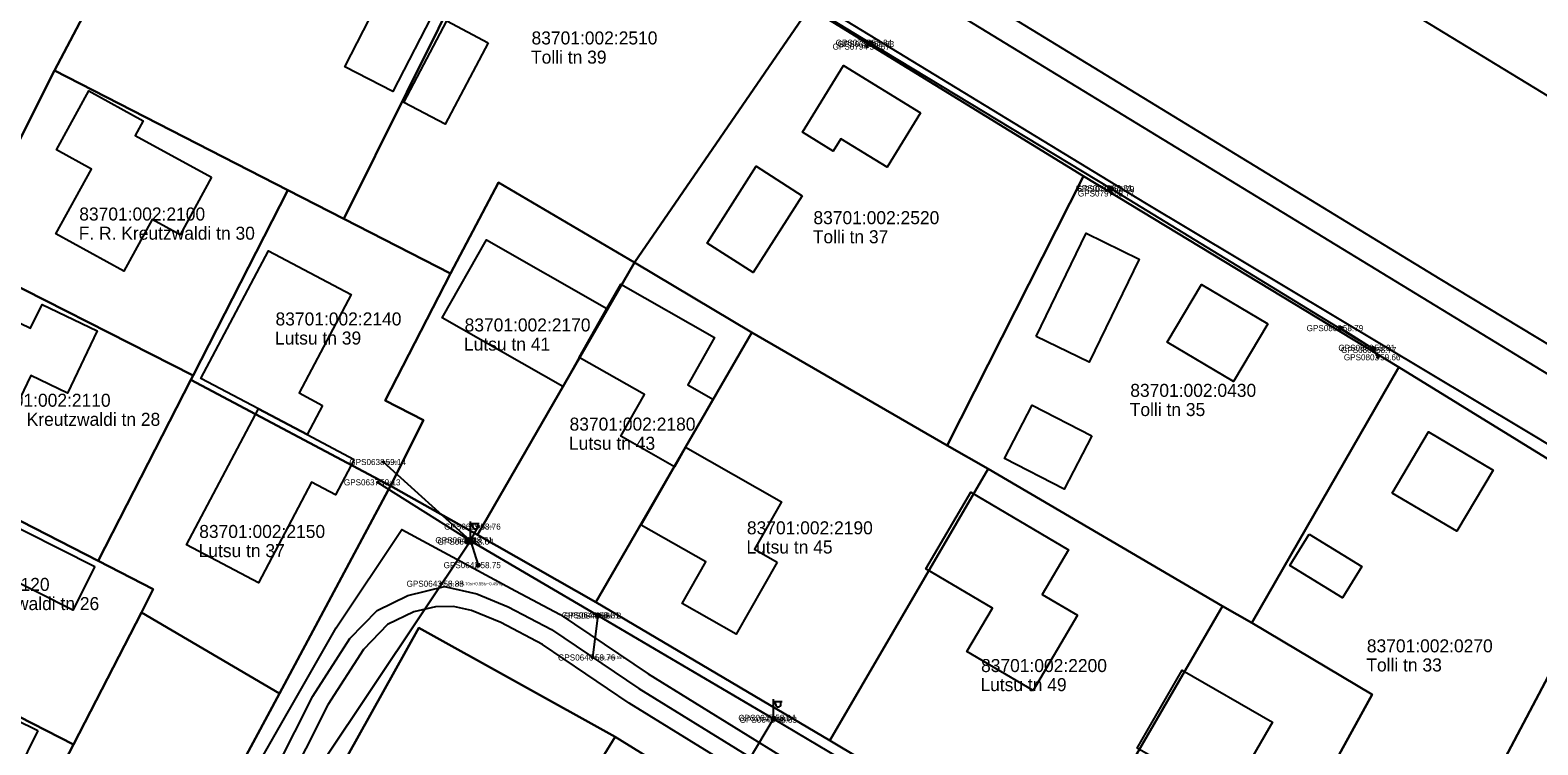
# Model space of a CAD drawing. Extents: x 580119 to 583377, y 6518915 to 6520820.
# Drawn here: x 581772.7 to 581946.3, y 6520373 to 6520455.4 of the extents above; entities that cross this region are included whole.
import ezdxf

# ---------------------------------------------------------------- set-up
doc = ezdxf.new("R2010")
doc.units = 0
for name, color, linetype in [('Hoone Elu- või ühiskondlik hoone', 7, 'Continuous'), ('Hoone Kõrval- või tootmishoone', 7, 'Continuous'), ('L_AADRESS', 7, 'Continuous'), ('MAAMUDEL', 7, 'Continuous'), ('MOOTKORG-EH2000', 7, 'Continuous'), ('MOOTMPUNKT', 7, 'Continuous'), ('MOOTNR', 7, 'Continuous'), ('MPOHULIIN', 7, 'Continuous'), ('Muu rajatis Katusealune', 7, 'Continuous'), ('PIIR', 7, 'Continuous'), ('POST', 7, 'Continuous'), ('Rippe kõrgus', 7, 'Continuous'), ('SIOHULIIN', 7, 'Continuous'), ('SIRAJATIS', 7, 'Continuous'), ('Tee Liiklusala', 7, 'Continuous'), ('Tee Tänav Püsikate', 7, 'Continuous'), ('TUNNUS', 7, 'Continuous')]:
    doc.layers.add(name, color=color, linetype=linetype)

msp = doc.modelspace()

# ---------------------------------------------------------------- linework, layer by layer
at = {"layer": 'Hoone Elu- või ühiskondlik hoone'}
for points in [[(581875.22, 6520445.82), (581871.37, 6520439.57), (581866.03, 6520442.86), (581865.14, 6520441.43), (581861.61, 6520443.61), (581866.34, 6520451.29)], [(581793.56, 6520438.41), (581789.93, 6520431.77), (581786.72, 6520433.53), (581783.46, 6520427.59), (581775.63, 6520431.89), (581779.72, 6520439.34), (581775.68, 6520441.56), (581779.41, 6520448.36), (581785.68, 6520444.93), (581784.75, 6520443.23)], [(581835.89, 6520417.66), (581834, 6520414.32), (581820.1, 6520422.21), (581825.21, 6520431.2), (581839.1, 6520423.3)], [(581806.32, 6520412.13), (581804.55, 6520408.77), (581798.95, 6520411.72), (581792.33, 6520415.21), (581800.1, 6520429.92), (581809.62, 6520424.9), (581803.63, 6520413.56)], [(581848.14, 6520407.3), (581846.87, 6520405.06), (581840.68, 6520408.58), (581843.41, 6520413.38), (581835.89, 6520417.66), (581839.1, 6520423.3), (581840.69, 6520426.09), (581851.49, 6520419.95), (581848.4, 6520414.5), (581851.3, 6520412.85)], [(581915.21, 6520421.53), (581911.28, 6520414.89), (581903.64, 6520419.42), (581907.57, 6520426.07)], [(581766.49, 6520424.01), (581772.7, 6520421.03), (581774.02, 6520423.77), (581780.39, 6520420.71), (581776.95, 6520413.54), (581772.73, 6520415.56), (581768.25, 6520406.24), (581759.9, 6520410.25)], [(581809.98, 6520405.89), (581807.83, 6520401.82), (581805.07, 6520403.27), (581798.94, 6520391.68), (581790.66, 6520396.05), (581798.95, 6520411.72), (581804.55, 6520408.77)], [(581929.56, 6520402.03), (581933.74, 6520409.08), (581941.18, 6520404.66), (581937, 6520397.62)], [(581858.71, 6520394.08), (581853.98, 6520385.76), (581847.77, 6520389.29), (581850.5, 6520394.1), (581843.05, 6520398.33), (581846.87, 6520405.06), (581848.14, 6520407.3), (581859.21, 6520401), (581856.11, 6520395.55)], [(581893.3, 6520387.96), (581888.2, 6520379.29), (581880.57, 6520383.78), (581883.5, 6520388.76), (581875.81, 6520393.3), (581881, 6520402.11), (581892.26, 6520395.49), (581889.23, 6520390.35)], [(581915.6, 6520368.18), (581911.32, 6520360.75), (581905.69, 6520363.98), (581908.05, 6520368.09), (581900.19, 6520372.62), (581905.37, 6520381.61), (581915.75, 6520375.63), (581912.49, 6520369.96)]]:
    msp.add_lwpolyline(points, close=True, dxfattribs=at)
at = {"layer": 'Hoone Kõrval- või tootmishoone'}
for points in [[(581819.45, 6520458.04), (581814.45, 6520448.29), (581808.89, 6520451.14), (581813.9, 6520460.89)], [(581825.43, 6520453.92), (581820.46, 6520444.52), (581815.7, 6520447.04), (581820.64, 6520456.44)], [(581861.58, 6520436.29), (581855.93, 6520427.45), (581850.64, 6520430.83), (581856.28, 6520439.68)], [(581888.52, 6520420.07), (581894.28, 6520431.96), (581900.41, 6520428.99), (581894.65, 6520417.1)], [(581894.94, 6520408.63), (581891.77, 6520402.47), (581884.9, 6520406.02), (581888.08, 6520412.17)], [(581780.11, 6520393.55), (581777.57, 6520388.54), (581765.58, 6520394.57), (581768.12, 6520399.6)], [(581773.53, 6520374.68), (581771.16, 6520369.84), (581758.58, 6520375.99), (581760.95, 6520380.84)]]:
    msp.add_lwpolyline(points, close=True, dxfattribs=at)
at = {"layer": 'MOOTMPUNKT'}
for centre in [(581869.08, 6520453.47), (581869.35, 6520453.92), (581869.57, 6520453.77), (581897.01, 6520437.16), (581897.24, 6520437.06), (581897.26, 6520436.55), (581923.61, 6520421.03), (581927.27, 6520418.76), (581927.43, 6520418.52), (581927.9, 6520417.67), (581813.34, 6520405.6), (581812.71, 6520403.26), (581824.26, 6520398.16), (581823.32, 6520396.59), (581823.44, 6520396.42), (581824.27, 6520393.72), (581820, 6520391.58), (581837.95, 6520387.95), (581838.14, 6520387.89), (581837.45, 6520383.08), (581858.22, 6520376.12), (581858.37, 6520375.9)]:
    msp.add_circle(centre, 0.1, dxfattribs=at)
at = {"layer": 'MPOHULIIN'}
for p, q in [((581869.46, 6520453.85), (581869.08, 6520453.47)), ((581897.12, 6520437.11), (581897.26, 6520436.55)), ((581823.38, 6520396.51), (581813.34, 6520405.6)), ((581812.71, 6520403.26), (581823.38, 6520396.51)), ((581823.38, 6520396.51), (581824.26, 6520398.16)), ((581838.05, 6520387.92), (581837.45, 6520383.08))]:
    msp.add_line(p, q, dxfattribs=at)
for points in [[(581788.5, 6520502.77), (581814.76, 6520487.31), (581837.78, 6520473.2), (581869.46, 6520453.85), (581897.12, 6520437.11), (581927.35, 6520418.64), (581927.9, 6520417.67)], [(581789.29, 6520345.21), (581806.35, 6520371.05), (581823.38, 6520396.51), (581838.05, 6520387.92), (581858.29, 6520376.01), (581878.69, 6520363.88), (581896.57, 6520352.92)]]:
    msp.add_lwpolyline(points, dxfattribs=at)
at = {"layer": 'Muu rajatis Katusealune'}
msp.add_lwpolyline([(581919.98, 6520397.29), (581926.05, 6520393.58), (581923.84, 6520389.96), (581917.77, 6520393.68)], close=True, dxfattribs=at)
at = {"layer": 'PIIR'}
for points in [[(581372.45, 6520790.36), (581408.38, 6520769.85), (581413.58, 6520742.25), (581463.7, 6520713.56), (581523.82, 6520679.13), (581549.51, 6520667), (581649.11, 6520606.32), (581652.65, 6520627.42), (582182.6, 6520304.58), (582184, 6520303.69), (582181.07, 6520288.42), (582278.18, 6520283.9), (582336.7, 6520285.99)], [(581799.11, 6520495.6), (581775.47, 6520450.71), (581764.63, 6520429.16)], [(582284.12, 6520257.02), (582261.11, 6520257.72), (582237.89, 6520257.97), (582223.55, 6520256.24), (582192.17, 6520260.67), (582164.12, 6520273.34), (582126.68, 6520296.88), (582094.75, 6520316.22), (582063.67, 6520335.59), (582031.69, 6520354.73), (581999.92, 6520374.14), (581993.27, 6520378.24), (581957.49, 6520399.79), (581930.32, 6520416.52), (581894, 6520438.54), (581862.44, 6520457.93)], [(581785.35, 6520349.14), (581801.36, 6520378.94), (581814.15, 6520402.85), (581824.17, 6520397.21), (581837.82, 6520389.46), (581864.77, 6520373.51), (581891.69, 6520357.4)]]:
    msp.add_lwpolyline(points, dxfattribs=at)
for points in [[(581830.55, 6520477.44), (581808.78, 6520433.62), (581802.33, 6520436.92), (581775.47, 6520450.71), (581799.11, 6520495.6)], [(581830.55, 6520477.44), (581862.44, 6520457.93), (581842.26, 6520428.59), (581826.59, 6520437.81), (581821.07, 6520427.33), (581808.78, 6520433.62)], [(581862.44, 6520457.93), (581894, 6520438.54), (581878.29, 6520407.51), (581855.8, 6520420.54), (581842.26, 6520428.59)], [(581775.47, 6520450.71), (581802.33, 6520436.92), (581791.42, 6520415.56), (581764.63, 6520429.16)], [(581821.07, 6520427.33), (581826.59, 6520437.81), (581842.26, 6520428.59), (581824.17, 6520397.21), (581814.15, 6520402.85), (581817.98, 6520410.44), (581813.53, 6520412.71)], [(581878.29, 6520407.51), (581894, 6520438.54), (581930.32, 6520416.52), (581913.4, 6520387.09), (581910, 6520388.99), (581883.02, 6520404.8)], [(581791.42, 6520415.56), (581802.33, 6520436.92), (581808.78, 6520433.62), (581821.07, 6520427.33), (581813.53, 6520412.71), (581817.98, 6520410.44), (581814.15, 6520402.85), (581791.17, 6520415.07)], [(581764.63, 6520429.16), (581791.42, 6520415.56), (581791.17, 6520415.07), (581780.5, 6520394.2), (581753.86, 6520407.85)], [(581842.26, 6520428.59), (581855.8, 6520420.54), (581837.82, 6520389.46), (581824.17, 6520397.21)], [(581855.8, 6520420.54), (581878.29, 6520407.51), (581883.02, 6520404.8), (581864.77, 6520373.51), (581837.82, 6520389.46)], [(581930.32, 6520416.52), (581957.49, 6520399.79), (581932.94, 6520353.26), (581931.31, 6520350.19), (581927.81, 6520351.97), (581921.06, 6520341.05), (581910.1, 6520322.74), (581906.17, 6520340.51), (581909.67, 6520346.83), (581927.24, 6520378.81), (581913.4, 6520387.09)], [(581791.17, 6520415.07), (581814.15, 6520402.85), (581801.36, 6520378.94), (581785.47, 6520388.28), (581786.84, 6520390.94), (581780.5, 6520394.2)], [(581753.86, 6520407.85), (581780.5, 6520394.2), (581786.84, 6520390.94), (581785.47, 6520388.28), (581777.64, 6520373.06), (581744.38, 6520390.07)], [(581883.02, 6520404.8), (581910, 6520388.99), (581891.69, 6520357.4), (581864.77, 6520373.51)], [(581957.49, 6520399.79), (581993.27, 6520378.24), (581969.51, 6520335.03), (581932.94, 6520353.26)], [(581744.38, 6520390.07), (581777.64, 6520373.06), (581769.84, 6520358.07), (581768.32, 6520355.34), (581735.49, 6520372.19)], [(581910, 6520388.99), (581913.4, 6520387.09), (581927.24, 6520378.81), (581909.67, 6520346.83), (581891.69, 6520357.4)], [(581769.84, 6520358.07), (581777.64, 6520373.06), (581785.47, 6520388.28), (581801.36, 6520378.94), (581785.35, 6520349.14), (581782.27, 6520350.98), (581774.1, 6520355.46)], [(581817.44, 6520386.49), (581840.03, 6520373.94), (581829.56, 6520356.9), (581832.75, 6520354.9), (581821.38, 6520336.91), (581798.19, 6520351.98)], [(581798.19, 6520351.98), (581821.38, 6520336.91), (581844, 6520323.04), (581878.03, 6520302.4), (581885.96, 6520304.82), (581899.19, 6520326.8), (581895.57, 6520340), (581865.29, 6520358.29), (581840.03, 6520373.94), (581817.44, 6520386.49)], [(581832.75, 6520354.9), (581829.56, 6520356.9), (581840.03, 6520373.94), (581865.29, 6520358.29), (581844, 6520323.04), (581821.38, 6520336.91)]]:
    msp.add_lwpolyline(points, close=True, dxfattribs=at)
at = {"layer": 'POST'}
for p, q in [((581823.38, 6520396.76), (581823.38, 6520398.76)), ((581823.38, 6520398.51), (581824.38, 6520398.51)), ((581823.6, 6520398.19), (581823.6, 6520398.51)), ((581824.22, 6520398.19), (581824.22, 6520398.51)), ((581823.38, 6520396.51), (581823.38, 6520396.51)), ((581858.29, 6520376.26), (581858.29, 6520378.26)), ((581858.29, 6520378.01), (581859.29, 6520378.01)), ((581858.52, 6520377.69), (581858.52, 6520378.01)), ((581859.13, 6520377.69), (581859.13, 6520378.01)), ((581858.29, 6520376.01), (581858.29, 6520376.01))]:
    msp.add_line(p, q, dxfattribs=at)
for points in [[(581927.35, 6520418.64), (581923.61, 6520421.03)], [(581823.38, 6520396.51), (581824.27, 6520393.72)]]:
    msp.add_lwpolyline(points, dxfattribs=at)
for centre, radius in [((581869.46, 6520453.85), 0.25), ((581897.12, 6520437.11), 0.25), ((581923.61, 6520421.03), 0.2), ((581927.35, 6520418.64), 0.25), ((581823.38, 6520396.51), 0.25), ((581824.27, 6520393.72), 0.2), ((581838.05, 6520387.92), 0.25), ((581858.29, 6520376.01), 0.25)]:
    msp.add_circle(centre, radius, dxfattribs=at)
for centre in [(581823.91, 6520398.19), (581858.83, 6520377.69)]:
    msp.add_arc(centre, 0.306, 180, 0, dxfattribs=at)
at = {"layer": 'SIOHULIIN'}
for points in [[(581689.69, 6520563.6), (581714.9, 6520547.97), (581754.92, 6520523.74), (581788.5, 6520502.77), (581814.76, 6520487.31), (581837.78, 6520473.2), (581869.46, 6520453.85), (581897.12, 6520437.11), (581927.35, 6520418.64)], [(581851.67, 6520364.92), (581858.29, 6520376.01), (581838.05, 6520387.92), (581823.38, 6520396.51), (581806.35, 6520371.05), (581789.29, 6520345.21), (581821.56, 6520325.5), (581843.02, 6520312.69)]]:
    msp.add_lwpolyline(points, dxfattribs=at)
at = {"layer": 'SIRAJATIS'}
msp.add_lwpolyline([(581822.88, 6520396.81), (581823.88, 6520396.81), (581823.88, 6520396.21), (581822.88, 6520396.21)], close=True, dxfattribs=at)
for centre, radius in [((581823.18, 6520396.51), 0.0304), ((581823.18, 6520396.51), 0.029), ((581823.18, 6520396.51), 0.0277), ((581823.18, 6520396.51), 0.0263), ((581823.18, 6520396.51), 0.0249), ((581823.18, 6520396.51), 0.0236), ((581823.18, 6520396.51), 0.0222), ((581823.18, 6520396.51), 0.0209), ((581823.18, 6520396.51), 0.0195), ((581823.18, 6520396.51), 0.0181), ((581823.18, 6520396.51), 0.0168), ((581823.18, 6520396.51), 0.0154), ((581823.18, 6520396.51), 0.014), ((581823.18, 6520396.51), 0.0127), ((581823.18, 6520396.51), 0.0113), ((581823.18, 6520396.51), 0.00996), ((581823.18, 6520396.51), 0.0086), ((581823.18, 6520396.51), 0.00724), ((581823.18, 6520396.51), 0.00587), ((581823.18, 6520396.51), 0.00451), ((581823.18, 6520396.51), 0.00315), ((581823.18, 6520396.51), 0.00179), ((581823.18, 6520396.51), 0.000426), ((581823.58, 6520396.51), 0.0304), ((581823.58, 6520396.51), 0.029), ((581823.58, 6520396.51), 0.0277), ((581823.58, 6520396.51), 0.0263), ((581823.58, 6520396.51), 0.0249), ((581823.58, 6520396.51), 0.0236), ((581823.58, 6520396.51), 0.0222), ((581823.58, 6520396.51), 0.0209), ((581823.58, 6520396.51), 0.0195), ((581823.58, 6520396.51), 0.0181), ((581823.58, 6520396.51), 0.0168), ((581823.58, 6520396.51), 0.0154), ((581823.58, 6520396.51), 0.014), ((581823.58, 6520396.51), 0.0127), ((581823.58, 6520396.51), 0.0113), ((581823.58, 6520396.51), 0.00996), ((581823.58, 6520396.51), 0.0086), ((581823.58, 6520396.51), 0.00724), ((581823.58, 6520396.51), 0.00587), ((581823.58, 6520396.51), 0.00451), ((581823.58, 6520396.51), 0.00315), ((581823.58, 6520396.51), 0.00179), ((581823.58, 6520396.51), 0.000426)]:
    msp.add_circle(centre, radius, dxfattribs=at)
at = {"layer": 'Tee Liiklusala'}
for points in [[(581642.24, 6520605.03), (581666.59, 6520590.06), (581670.59, 6520587.55), (581796.41, 6520511.4), (581835.2, 6520487.74), (581935.02, 6520426.71), (581983.36, 6520397.53), (582007.48, 6520382.93), (582088.2, 6520334.1), (582141.71, 6520301.56), (582165.37, 6520287.35), (582174.12, 6520281.61), (582181.2, 6520277.68), (582186.15, 6520275.41), (582189.6, 6520274.06), (582195.31, 6520272.25), (582202.65, 6520270.15), (582210.44, 6520268.42), (582213.27, 6520268.02)], [(581970.52, 6520393.78), (581944.66, 6520409.33), (581901.07, 6520435.48), (581799.08, 6520497.66)], [(581786.01, 6520348.21), (581807.9, 6520386.5), (581815.46, 6520397.82), (581828.57, 6520390.74), (581833.72, 6520388.03), (581843.85, 6520381.18), (581859.87, 6520371.29)], [(581857.8, 6520367.86), (581841.67, 6520377.82), (581831.66, 6520384.59), (581826.87, 6520387.11), (581823.51, 6520388.5), (581821.41, 6520388.94), (581819.33, 6520388.93), (581816.85, 6520388.32), (581813.8, 6520386.86), (581811.05, 6520384), (581806.94, 6520377.64), (581796.75, 6520357.42)]]:
    msp.add_lwpolyline(points, dxfattribs=at)
at = {"layer": 'Tee Tänav Püsikate'}
for points in [[(582000.38, 6520383.48), (581949.86, 6520414.26), (581890.19, 6520450.69), (581837.18, 6520483.09), (581794.85, 6520508.84)], [(581829.4, 6520325.26), (581818.11, 6520332.41), (581802.94, 6520342.03), (581797.05, 6520345.98), (581794.58, 6520349.99), (581793.88, 6520354.52), (581794.87, 6520358.14), (581805.2, 6520378.63), (581809.48, 6520385.25), (581812.61, 6520388.5), (581816.17, 6520390.21), (581820.37, 6520391.25), (581824.11, 6520390.41), (581827.72, 6520388.92), (581832.69, 6520386.31), (581842.76, 6520379.5), (581858.83, 6520369.58), (581884.17, 6520354.62), (581894.53, 6520347.73), (581898.23, 6520344.36), (581900.37, 6520340.47), (581901.81, 6520333.85), (581904.24, 6520320.68), (581905.59, 6520312.25)]]:
    msp.add_lwpolyline(points, dxfattribs=at)

# ---------------------------------------------------------------- texts
at = {"layer": 'L_AADRESS'}
for s, p in [('Tolli tn 39', (581830.35, 6520451.51)), ('F. R. Kreutzwaldi tn 30', (581778.25, 6520431.22)), ('Tolli tn 37', (581862.81, 6520430.81)), ('Lutsu tn 39', (581800.86, 6520419.14)), ('Lutsu tn 41', (581822.63, 6520418.44)), ('F. R. Kreutzwaldi tn 28', (581767.35, 6520409.77)), ('Tolli tn 35', (581899.32, 6520410.9)), ('Lutsu tn 43', (581834.72, 6520407.01)), ('Lutsu tn 37', (581792.06, 6520394.64)), ('Lutsu tn 45', (581855.16, 6520395.06)), ('F. R. Kreutzwaldi tn 26', (581760.32, 6520388.54)), ('Tolli tn 33', (581926.57, 6520381.47)), ('Lutsu tn 49', (581882.12, 6520379.2))]:
    msp.add_text(s, height=1.5, dxfattribs=at).set_placement(p)
at = {"layer": 'MAAMUDEL'}
for s, p in [(' mp_ohl', (581813.34, 6520405.43)), (' mp_ohl', (581812.71, 6520403.08)), (' mp_ohl', (581824.26, 6520397.98)), (' kaabel', (581837.95, 6520387.77)), (' kaabel', (581838.14, 6520387.71)), (' kaabel', (581858.22, 6520375.95)), (' kaabel', (581858.37, 6520375.72))]:
    msp.add_text(s, height=0.35, dxfattribs=at).set_placement(p)
at = {"layer": 'MOOTKORG-EH2000'}
for s, p in [(' 58.67', (581869.08, 6520453.12)), (' 58.84', (581869.35, 6520453.57)), (' 58.83', (581869.57, 6520453.42)), (' 58.81', (581897.01, 6520436.81)), (' 58.79', (581897.24, 6520436.71)), (' 58.77', (581897.26, 6520436.2)), (' 58.79', (581923.61, 6520420.68)), (' 58.81', (581927.27, 6520418.41)), (' 58.77', (581927.43, 6520418.17)), (' 59.66', (581927.9, 6520417.32)), (' 59.14', (581813.34, 6520405.25)), (' 59.13', (581812.71, 6520402.91)), (' 58.76', (581824.26, 6520397.81)), (' 58.71', (581823.32, 6520396.24)), (' 58.64', (581823.44, 6520396.07)), (' 58.75', (581824.27, 6520393.37)), (' 58.88', (581820, 6520391.23)), (' 58.81', (581837.95, 6520387.6)), (' 58.78', (581838.14, 6520387.54)), (' 58.76', (581837.45, 6520382.73)), (' 58.64', (581858.22, 6520375.77)), (' 58.63', (581858.37, 6520375.55))]:
    msp.add_text(s, height=0.7, dxfattribs=at).set_placement(p)
at = {"layer": 'MOOTNR'}
for s, p in [('GPS0794 ', (581865.09, 6520453.12)), ('GPS0795 ', (581865.44, 6520453.57)), ('GPS0796 ', (581865.65, 6520453.42)), ('GPS0799 ', (581893.09, 6520436.81)), ('GPS0798 ', (581893.32, 6520436.71)), ('GPS0797 ', (581893.34, 6520436.2)), ('GPS0800 ', (581919.69, 6520420.68)), ('GPS0802 ', (581923.35, 6520418.41)), ('GPS0801 ', (581923.65, 6520418.17)), ('GPS0803 ', (581923.98, 6520417.32)), ('GPS0638 ', (581809.42, 6520405.25)), ('GPS0637 ', (581808.79, 6520402.91)), ('GPS0639 ', (581820.34, 6520397.81)), ('GPS0640 ', (581819.33, 6520396.24)), ('GPS0641 ', (581819.59, 6520396.07)), ('GPS0642 ', (581820.28, 6520393.37)), ('GPS0643 ', (581816.01, 6520391.23)), ('GPS0644 ', (581833.89, 6520387.6)), ('GPS0645 ', (581834.15, 6520387.54)), ('GPS0646 ', (581833.46, 6520382.73)), ('GPS0647 ', (581854.23, 6520375.77)), ('GPS0648 ', (581854.38, 6520375.55))]:
    msp.add_text(s, height=0.7, dxfattribs=at).set_placement(p)
at = {"layer": 'Rippe kõrgus'}
for s, p in [(' el_mp_ohl5.70si+0.55tv+0.45mp', (581820, 6520391.4)), (' el_mp_ohl6.55m', (581837.45, 6520382.9))]:
    msp.add_text(s, height=0.35, dxfattribs=at).set_placement(p)
at = {"layer": 'TUNNUS'}
for s, p in [('83701:002:2510', (581830.41, 6520453.72)), ('83701:002:2100', (581778.31, 6520433.43)), ('83701:002:2520', (581862.88, 6520433.01)), ('83701:002:2140', (581800.92, 6520421.34)), ('83701:002:2170', (581822.7, 6520420.65)), ('83701:002:2110', (581767.42, 6520411.97)), ('83701:002:0430', (581899.38, 6520413.11)), ('83701:002:2180', (581834.79, 6520409.22)), ('83701:002:2150', (581792.13, 6520396.85)), ('83701:002:2190', (581855.22, 6520397.27)), ('83701:002:2120', (581760.39, 6520390.75)), ('83701:002:0270', (581926.63, 6520383.67)), ('83701:002:2200', (581882.19, 6520381.4))]:
    msp.add_text(s, height=1.5, dxfattribs=at).set_placement(p)

doc.saveas('drawing.dxf')
